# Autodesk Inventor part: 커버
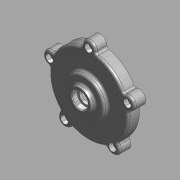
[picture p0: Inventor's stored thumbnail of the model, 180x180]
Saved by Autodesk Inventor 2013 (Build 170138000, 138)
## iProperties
Created: 2015-11
Part Number: 커버
Document SubType Name: 모델링
Designer: mdu
Material: 알루미늄 6061
Density: 2.71 g/cm^3
Mass: 201.191 g
Surface Area: 286.328 cm^2
Volume: 74.2403 cm^3
변환 표준: STEP AP214IS
파일 이름: C:\Users\SeoGD\Desktop\?쒗뿕\而ㅻ쾭-1.stp
전처리기: Build: 253, Release: 2010 SP1 - Date: Wed 07/29/2009
전송 단위: 밀리미터
불확실성: 0.01
Author: mdu
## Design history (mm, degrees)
sketch "스케치1"
  geometry: L1 (0, 0)-(0, 26); L2 (50, 0)-(50, 15); L3 (50, 15)-(25, 15); L4 (25, 15)-(25, 21); L5 (25, 21)-(15, 21); L6 (15, 21)-(13.66, 26); L7 (13.66, 26)-(10, 26); L8 (50, 0)-(45, 0); L9 (45, 0)-(45, 10); L10 (45, 10)-(14.5, 10); L11 (14.5, 10)-(13.266, 3); L12 (13.266, 3)-(11, 3); L13 (11, 3)-(11, 16); L14 (11, 16)-(7.5, 16); L15 (7.5, 16)-(7.5, 19); L16 (7.5, 19)-(10, 19); L17 (10, 19)-(10, 26)
  constraints: 34 end point, 10 parallel, 2 perpendicular, 2 point on line, 1 vertical
  dimensions: "d11" = 100 diameter of L2 L1; "d12" = 22 diameter of L13 L1; "d13" = 90 diameter of L9 L1; "d14" = 15 distance between parallel lines of L3 L8; "d15" = 10 distance between parallel lines of L8 L10; "d16" = 29 diameter of L10.end L1; "d17" = 100 deg angle of L11 L10; "d18" = 7 distance between parallel lines of L12 L10; "d19" = 13 distance between parallel lines of L14 L12; "d20" = 3 distance between parallel lines of L16 L14; "d21" = 15 diameter of L15 L1; "d22" = 20 diameter of L17 L1; "d23" = 30 diameter of L5.end L1; "d24" = 6 distance between parallel lines of L5 L3; "d25" = 50 diameter of L4 L1; "d26" = 105 deg angle of L5 L6; "d50" = 26 distance of L1.start L1.end
revolve "회전1" sketch "스케치1" stored, may be unused: angle "d27" = 90 deg
sketch "스케치2" dims "d29" = 104
  geometry: A1 r 8.5 centre (0, 52) between (8.074, 49.344) and (-8.074, 49.344); A2 r 50 centre (0, 0) between (-8.074, 49.344) and (8.074, 49.344) reference; 2 further points
  constraints: 4 point on circle, 2 vertical alignment, 1 centre point, 1 coincident, 2 other
  dimensions: "d28" = 17 diameter of A1
extrude "돌출1" join sketch "스케치2" stored distance "d30" = 10; taper "d31" = 0 deg
fillet "모깎기3" dims "d32" = 3
fillet "모깎기4" dims "d45" = 3, "d46" = 0.2
chamfer "모따기1" distance "d47" = 1; stored, may be unused: second distance "d48" = 2, angle "d49" = 45 deg
hole "구멍2" diameter "d38" = 5.5; stored, may be unused: countersink angle "d42" = 90 deg, drill point angle "d44" = 118 deg; dims "d36" = 10, "d37" = 10, "d39" = 6, "d40" = 9.5, "d41" = 5.4, "d43" = 8
node "솔리드1"
node "솔리드 본체"
node "곡면 본체"
pattern_circular "원형 패턴1" dims angle "d34" = 360 deg
pattern_circular "원형 패턴2" dims angle "d52" = 360 deg
node "솔리드2"
